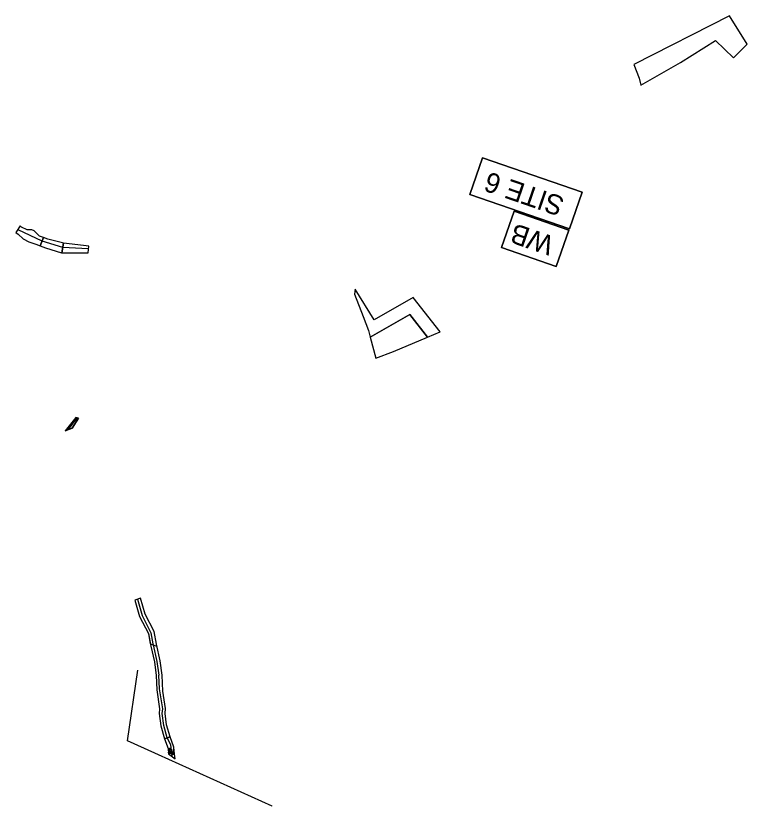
# Model space of a CAD drawing. Extents: x 474218 to 481634, y 484357 to 504997.
# Drawn here: x 480709 to 481261, y 492929 to 493526 of the extents above; entities that cross this region are included whole.
import ezdxf

# ---------------------------------------------------------------- set-up
doc = ezdxf.new("R2010")
doc.units = 0
for name, color, linetype in [('Exist Hydro Swamp or Marsh Text', 7, 'Continuous'), ('Old_Level_29', 7, 'Continuous'), ('Old_Level_30', 7, 'Continuous'), ('Prop Boundary Clearing Mechanized Hatching CELL', 7, 'Continuous'), ('Prop Earthen Structure Fill In Wetlands Hatching CELL', 7, 'Continuous'), ('Prop Earthen Structure Impacts In Surface Waters Hatching CELL', 7, 'Continuous'), ('Prop Grid Mask', 7, 'Continuous'), ('Scratch_Level_4', 7, 'Continuous'), ('Temp Earthen Structure Impacts In Surface Waters Hatching CELL', 7, 'Continuous')]:
    doc.layers.add(name, color=color, linetype=linetype)

msp = doc.modelspace()

# ---------------------------------------------------------------- linework, layer by layer
at = {"layer": 'Exist Hydro Swamp or Marsh Text'}
msp.add_line((480810.26, 493051.98), (480815.19, 493050.31), dxfattribs=at)
for points in [[(480815.19, 493050.31), (480814.87, 493051.7), (480813.15, 493061.2), (480806.4, 493074.42), (480802.89, 493086.35), (480798.57, 493085.08), (480802.2, 493072.75), (480808.84, 493059.76), (480810.26, 493051.98)], [(480902.16, 492929.41), (480902.16, 492929.41), (480793.06, 492978.83), (480800.78, 493032.2)]]:
    msp.add_lwpolyline(points, dxfattribs=at)
at = {"layer": 'Old_Level_29'}
msp.add_lwpolyline([(481126.87, 493365.38), (481051.65, 493391.29), (481061.12, 493418.8), (481136.35, 493392.88)], close=True, dxfattribs=at)
at = {"layer": 'Old_Level_30'}
msp.add_lwpolyline([(481116.75, 493336.89), (481075.41, 493351.13), (481084.89, 493378.63), (481126.23, 493364.39)], close=True, dxfattribs=at)
at = {"layer": 'Prop Boundary Clearing Mechanized Hatching CELL'}
msp.add_lwpolyline([(481029.08, 493287.6), (481029.08, 493287.6), (481008.86, 493313.5), (480979.32, 493296.61), (480964.95, 493319.78), (480964.35, 493316.08), (480971.01, 493299), (480975.04, 493288.67), (480976.39, 493283.41), (481006.31, 493300.52), (481019.53, 493283.59), (481029.08, 493287.6)], dxfattribs=at)
at = {"layer": 'Prop Earthen Structure Fill In Wetlands Hatching CELL'}
for p, q in [((481019.53, 493283.59), (481006.31, 493300.52)), ((480976.39, 493283.41), (480980.43, 493267.71)), ((480993.78, 493272.78), (481019.53, 493283.59)), ((481019.53, 493283.59), (481019.53, 493283.59)), ((481019.53, 493283.59), (481019.53, 493283.59)), ((480980.43, 493267.71), (480993.78, 493272.78))]:
    msp.add_line(p, q, dxfattribs=at)
msp.add_lwpolyline([(481006.31, 493300.52), (481006.31, 493300.52), (480976.39, 493283.41)], dxfattribs=at)
at = {"layer": 'Prop Earthen Structure Impacts In Surface Waters Hatching CELL'}
for p, q in [((480743.38, 493347.31), (480744.81, 493354.55)), ((480754.09, 493222.78), (480746.01, 493212.87)), ((480751.11, 493214.93), (480756.02, 493222.28)), ((480756.02, 493222.28), (480754.09, 493222.78)), ((480746.01, 493212.87), (480751.11, 493214.93))]:
    msp.add_line(p, q, dxfattribs=at)
for points in [[(480744.81, 493354.55), (480744.81, 493354.55), (480744.81, 493354.55), (480743.87, 493354.66), (480732.78, 493357.51), (480729.5, 493358.71), (480727.16, 493352.37), (480727.16, 493352.37), (480727.16, 493352.37), (480731.09, 493350.87), (480743.21, 493347.31), (480743.38, 493347.31)], [(480814.87, 493051.7), (480813.15, 493061.2), (480806.4, 493074.42), (480802.89, 493086.35), (480798.57, 493085.08), (480802.2, 493072.75), (480808.84, 493059.76), (480810.59, 493050.2), (480813.3, 493038.42), (480814.62, 493028.19), (480815.22, 493017.23), (480817.14, 493003.04), (480816.83, 492999.31), (480818.16, 492989.97), (480820.86, 492980.31), (480825.15, 492981.7), (480822.58, 492990.9), (480821.36, 492999.44), (480821.67, 493003.2), (480819.77, 493016.18), (480819.14, 493028.34), (480817.73, 493039.21), (480814.87, 493051.7)]]:
    msp.add_lwpolyline(points, dxfattribs=at)
at = {"layer": 'Prop Grid Mask'}
for points in [[(481136.35, 493392.88), (481061.12, 493418.8), (481051.65, 493391.29), (481126.87, 493365.38)], [(481126.23, 493364.39), (481084.89, 493378.63), (481075.41, 493351.13), (481116.75, 493336.89)]]:
    msp.add_lwpolyline(points, close=True, dxfattribs=at)
at = {"layer": 'Scratch_Level_4'}
for p, q in [((480728.47, 493355.92), (480710.5, 493364.65)), ((480744.13, 493351.32), (480728.47, 493355.92)), ((480763.44, 493350.23), (480744.13, 493351.32)), ((480754.09, 493222.78), (480746.01, 493212.87)), ((480748.56, 493213.9), (480755.06, 493222.53)), ((480756.02, 493222.28), (480751.11, 493214.93)), ((480756.02, 493222.28), (480754.09, 493222.78)), ((480751.11, 493214.93), (480746.01, 493212.87))]:
    msp.add_line(p, q, dxfattribs=at)
msp.add_lwpolyline([(481250.63, 493494.42), (481260.98, 493504.65), (481247.66, 493526.14), (481175.34, 493489.45), (481179.37, 493479.11), (481180.72, 493473.86), (481210.64, 493490.97), (481237.05, 493507.49)], close=True, dxfattribs=at)
for points in [[(480800.49, 493085.64), (480804.06, 493073.49), (480810.76, 493060.4), (480812.23, 493051.92), (480812.39, 493051.24)], [(480812.39, 493051.24), (480815.27, 493038.77), (480816.63, 493028.26)], [(480822.97, 492980.96), (480820.44, 492990.28), (480819.17, 492999.4), (480819.61, 493002.99), (480817.31, 493017.91), (480816.63, 493028.26)], [(480822.97, 492980.96), (480822.97, 492980.96), (480825.41, 492975.74), (480826.47, 492967.15)]]:
    msp.add_lwpolyline(points, dxfattribs=at)
at = {"layer": 'Temp Earthen Structure Impacts In Surface Waters Hatching CELL'}
for p, q in [((480727.16, 493352.37), (480729.5, 493358.71)), ((480744.81, 493354.55), (480743.38, 493347.31))]:
    msp.add_line(p, q, dxfattribs=at)
for points in [[(480729.5, 493358.71), (480726.64, 493359.76), (480722.5, 493363.85), (480720.75, 493364.52), (480717.27, 493364.44), (480712.89, 493366.65), (480712.89, 493366.65), (480712.04, 493367.45), (480708.67, 493362.51), (480710.47, 493361.21), (480714.24, 493357.82), (480718.61, 493355.47), (480723.87, 493353.61), (480727.16, 493352.37)], [(480743.38, 493347.31), (480749.6, 493347.29), (480763.27, 493347.23), (480763.27, 493347.23), (480763.9, 493352.23), (480759.88, 493352.81)], [(480759.88, 493352.81), (480744.81, 493354.55), (480744.81, 493354.55)], [(480820.86, 492980.31), (480823.66, 492973), (480824, 492968.98), (480828.93, 492965.27), (480828.93, 492965.27), (480828.93, 492965.27), (480828.54, 492968.74), (480828.09, 492974.07), (480825.15, 492981.7), (480820.86, 492980.31)]]:
    msp.add_lwpolyline(points, dxfattribs=at)
for points in [[(480824.18, 492970.19), (480824.12, 492970.34), (480823.85, 492970.3), (480823.75, 492970.29), (480823.63, 492970.27), (480823.63, 492970.24), (480823.63, 492970.23), (480823.63, 492970.21), (480823.64, 492970.17), (480824.56, 492969.86), (480824.33, 492969.96), (480824.31, 492970), (480824.3, 492970.01), (480824.27, 492970.05), (480824.19, 492970.14)], [(480825.72, 492970.06), (480825.75, 492970.18), (480825.12, 492970.4), (480825.15, 492970.25), (480825.1, 492970.07), (480825.1, 492970.05), (480825.07, 492970.01), (480824.98, 492969.91), (480824.92, 492969.89), (480824.83, 492969.85), (480824.79, 492969.84), (480824.77, 492969.84), (480824.68, 492969.85), (480824.56, 492969.86), (480823.64, 492970.17), (480823.64, 492970.11), (480823.74, 492969.89), (480823.76, 492969.84), (480823.99, 492969.6), (480824.82, 492969.31), (480825.11, 492969.37), (480825.19, 492969.39), (480825.37, 492969.51), (480825.43, 492969.56), (480825.46, 492969.58), (480825.48, 492969.59), (480825.49, 492969.6), (480825.5, 492969.62), (480825.54, 492969.67), (480825.56, 492969.71), (480825.64, 492969.82), (480825.66, 492969.86), (480825.67, 492969.87)], [(480825.22, 492972.41), (480825.44, 492972.37), (480824.51, 492972.69), (480824.48, 492972.66), (480824.47, 492972.66), (480824.47, 492972.65), (480824.4, 492972.6), (480824.38, 492972.58), (480824.37, 492972.56), (480824.32, 492972.47), (480824.3, 492972.43), (480824.28, 492972.4), (480824.21, 492972.28), (480824.19, 492972.2), (480824.14, 492972.01), (480824.12, 492971.92), (480824.14, 492971.84), (480824.17, 492971.69), (480824.17, 492971.69), (480824.19, 492971.57), (480824.25, 492971.48), (480824.4, 492971.25), (480824.46, 492971.19), (480824.7, 492970.93), (480824.83, 492970.81), (480825.72, 492970.5), (480825.67, 492970.59), (480825.57, 492970.8), (480825.53, 492970.86), (480825.31, 492971.11), (480825.2, 492971.23), (480825.03, 492971.4), (480824.83, 492971.61), (480824.78, 492971.69), (480824.73, 492971.8), (480824.73, 492972.01), (480824.77, 492972.09), (480824.83, 492972.21), (480824.86, 492972.24), (480824.89, 492972.27), (480824.98, 492972.35), (480825.02, 492972.36), (480825.06, 492972.37), (480825.19, 492972.4), (480825.21, 492972.41)], [(480826.07, 492972.63), (480825.63, 492972.86), (480825.14, 492972.95), (480825.14, 492972.95), (480824.75, 492972.85), (480824.7, 492972.84), (480824.51, 492972.69), (480825.44, 492972.37), (480825.68, 492972.25), (480825.68, 492972.24), (480825.7, 492972.23), (480825.8, 492972.12), (480825.84, 492972.08), (480825.85, 492972.05), (480825.9, 492971.92), (480825.92, 492971.87), (480825.92, 492971.83), (480825.92, 492971.69), (480826.23, 492971.72), (480826.32, 492971.73), (480826.42, 492971.74), (480826.42, 492971.85), (480826.43, 492971.88), (480826.43, 492971.9), (480826.43, 492971.98), (480826.42, 492971.99), (480826.42, 492971.99), (480826.41, 492972.04), (480826.34, 492972.27), (480826.33, 492972.3), (480826.07, 492972.62)], [(480825.73, 492970.42), (480825.72, 492970.5), (480824.83, 492970.81), (480824.96, 492970.68), (480825.11, 492970.47), (480825.12, 492970.4), (480825.75, 492970.18), (480825.75, 492970.25)], [(480827.24, 492969.27), (480828.23, 492972.12), (480827.69, 492972.31), (480826.7, 492969.45)], [(480824.77, 492969.32), (480824.82, 492969.31), (480823.99, 492969.6), (480824, 492969.59), (480824.39, 492969.39), (480824.39, 492969.39)], [(480827.96, 492968.5), (480828.12, 492968.96), (480825.82, 492969.76), (480825.66, 492969.29)]]:
    msp.add_lwpolyline(points, close=True, dxfattribs=at)

# ---------------------------------------------------------------- texts
at = {"layer": 'Old_Level_29'}
msp.add_text('SITE 6', height=15, rotation=160.98959, dxfattribs=at).set_placement((481123.91, 493388.7))
at = {"layer": 'Old_Level_30'}
msp.add_text('WB', height=15, rotation=160.98959, dxfattribs=at).set_placement((481116.09, 493359.14))

doc.saveas('drawing.dxf')
